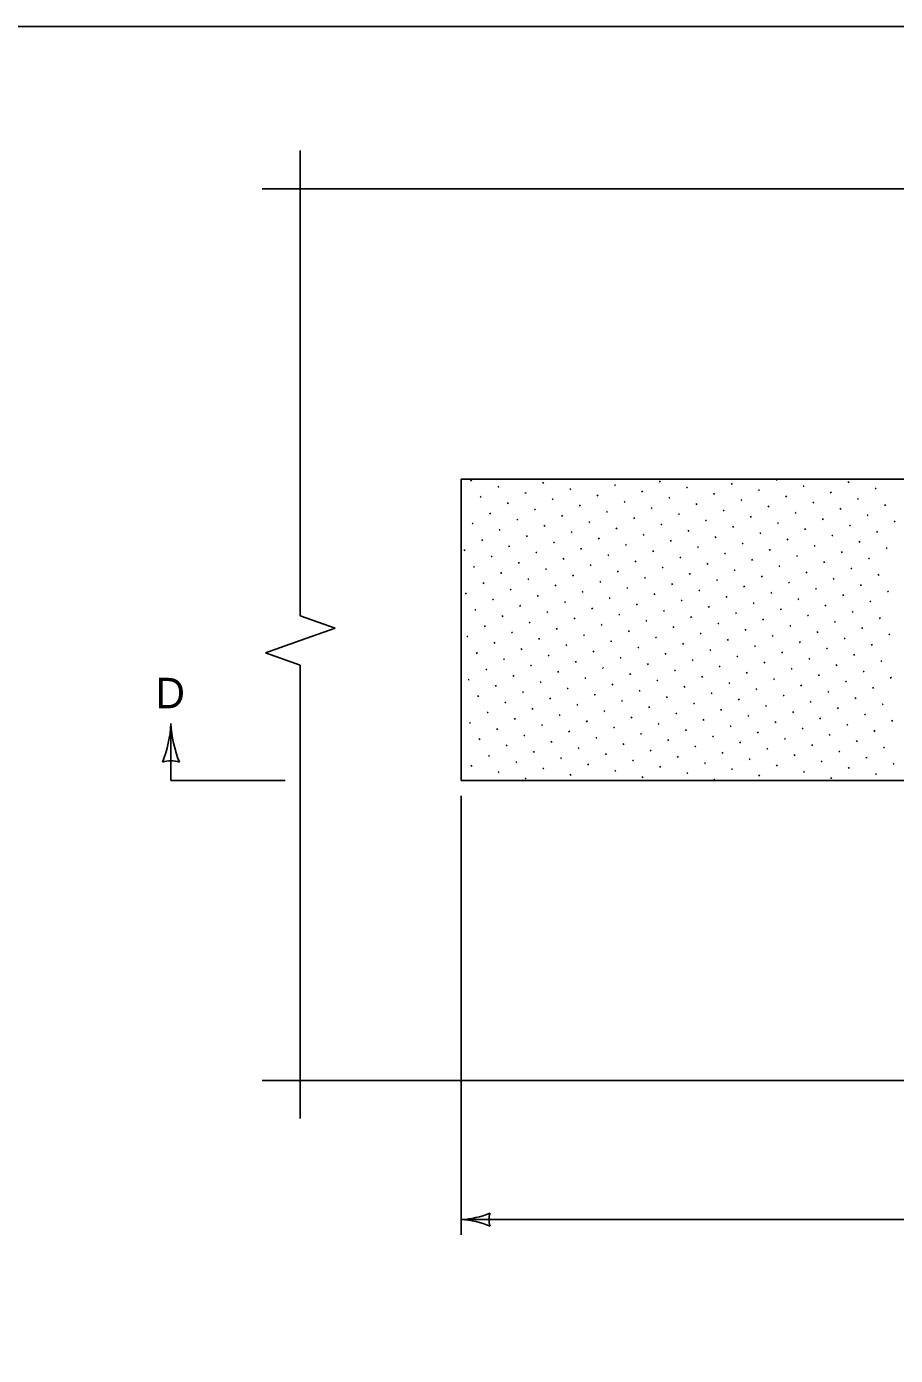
# Model space of a CAD drawing. Extents: x 49991.4 to 50021, y 49987.6 to 50011.4.
# Drawn here: x 50001.317 to 50003.6, y 49995.508 to 49998.999 of the extents above; entities that cross this region are included whole.
import ezdxf

# ---------------------------------------------------------------- set-up
doc = ezdxf.new("R2010")
doc.units = 0
for name, color, linetype in [('Level 1', 7, 'Continuous'), ('Level 2', 7, 'Continuous'), ('Level 3', 7, 'Continuous'), ('Level 6', 7, 'Continuous')]:
    doc.layers.add(name, color=color, linetype=linetype)

msp = doc.modelspace()

# ---------------------------------------------------------------- linework, layer by layer
at = {"layer": 'Level 1'}
for p, q in [((50002.4589, 49997.8102), (50013.6129, 49997.8102)), ((50002.4589, 49997.0183), (50002.4589, 49997.8102)), ((50013.6129, 49997.0183), (50002.4589, 49997.0183))]:
    msp.add_line(p, q, dxfattribs=at)
msp.add_lwpolyline([(49999.3835, 49998.9992), (50016.7501, 49998.9992), (50016.7501, 49987.7988), (49999.3835, 49987.7988)], close=True, dxfattribs=at)
at = {"layer": 'Level 3'}
for p, q in [((50002.4839, 49997.8061), (50002.487, 49997.8078)), ((50002.5553, 49997.7895), (50002.5583, 49997.7913)), ((50002.673, 49997.7997), (50002.676, 49997.8015)), ((50002.7906, 49997.8099), (50002.7911, 49997.8102)), ((50002.862, 49997.7934), (50002.865, 49997.7951)), ((50002.9797, 49997.8036), (50002.9827, 49997.8053)), ((50003.1687, 49997.7973), (50003.1717, 49997.799)), ((50003.2863, 49997.8075), (50003.2894, 49997.8092)), ((50003.3577, 49997.7909), (50003.3607, 49997.7927)), ((50003.4754, 49997.8011), (50003.4784, 49997.8029)), ((50002.5089, 49997.7628), (50002.512, 49997.7645)), ((50002.6266, 49997.773), (50002.6297, 49997.7747)), ((50002.698, 49997.7564), (50002.701, 49997.7582)), ((50002.7443, 49997.7832), (50002.7473, 49997.7849)), ((50002.8156, 49997.7666), (50002.8187, 49997.7684)), ((50002.9333, 49997.7768), (50002.9363, 49997.7786)), ((50003.0047, 49997.7603), (50003.0077, 49997.762)), ((50003.051, 49997.787), (50003.054, 49997.7888)), ((50003.1223, 49997.7705), (50003.1254, 49997.7722)), ((50003.24, 49997.7807), (50003.243, 49997.7825)), ((50003.3113, 49997.7642), (50003.3144, 49997.7659)), ((50003.429, 49997.7744), (50003.4321, 49997.7761)), ((50003.5004, 49997.7578), (50003.5034, 49997.7596)), ((50003.5467, 49997.7846), (50003.5497, 49997.7863)), ((50002.5339, 49997.7195), (50002.537, 49997.7212)), ((50002.5803, 49997.7462), (50002.5833, 49997.748)), ((50002.6516, 49997.7297), (50002.6547, 49997.7314)), ((50002.7693, 49997.7399), (50002.7723, 49997.7416)), ((50002.8406, 49997.7233), (50002.8437, 49997.7251)), ((50002.887, 49997.7501), (50002.89, 49997.7518)), ((50002.9583, 49997.7335), (50002.9613, 49997.7353)), ((50003.076, 49997.7437), (50003.079, 49997.7455)), ((50003.1473, 49997.7272), (50003.1504, 49997.7289)), ((50003.1937, 49997.754), (50003.1967, 49997.7557)), ((50003.265, 49997.7374), (50003.268, 49997.7392)), ((50003.3363, 49997.7209), (50003.3394, 49997.7226)), ((50003.3827, 49997.7476), (50003.3857, 49997.7494)), ((50003.454, 49997.7311), (50003.4571, 49997.7328)), ((50003.5717, 49997.7413), (50003.5747, 49997.743)), ((50002.4876, 49997.6927), (50002.4906, 49997.6945)), ((50002.6053, 49997.7029), (50002.6083, 49997.7047)), ((50002.6766, 49997.6864), (50002.6797, 49997.6881)), ((50002.723, 49997.7131), (50002.726, 49997.7149)), ((50002.7943, 49997.6966), (50002.7973, 49997.6983)), ((50002.912, 49997.7068), (50002.915, 49997.7085)), ((50002.9833, 49997.6902), (50002.9863, 49997.692)), ((50003.0297, 49997.717), (50003.0327, 49997.7187)), ((50003.101, 49997.7004), (50003.104, 49997.7022)), ((50003.2187, 49997.7107), (50003.2217, 49997.7124)), ((50003.29, 49997.6941), (50003.293, 49997.6959)), ((50003.4077, 49997.7043), (50003.4107, 49997.7061)), ((50003.479, 49997.6878), (50003.4821, 49997.6895)), ((50003.5254, 49997.7145), (50003.5284, 49997.7163)), ((50003.5967, 49997.698), (50003.5997, 49997.6997)), ((50002.5589, 49997.6762), (50002.562, 49997.6779)), ((50002.6303, 49997.6596), (50002.6333, 49997.6614)), ((50002.748, 49997.6698), (50002.751, 49997.6716)), ((50002.8193, 49997.6533), (50002.8223, 49997.655)), ((50002.8656, 49997.68), (50002.8687, 49997.6818)), ((50002.937, 49997.6635), (50002.94, 49997.6652)), ((50003.0547, 49997.6737), (50003.0577, 49997.6754)), ((50003.126, 49997.6571), (50003.129, 49997.6589)), ((50003.1723, 49997.6839), (50003.1754, 49997.6856)), ((50003.2437, 49997.6673), (50003.2467, 49997.6691)), ((50003.315, 49997.6508), (50003.318, 49997.6526)), ((50003.3613, 49997.6776), (50003.3644, 49997.6793)), ((50003.4327, 49997.661), (50003.4357, 49997.6628)), ((50003.5504, 49997.6712), (50003.5534, 49997.673)), ((50002.4663, 49997.6227), (50002.4693, 49997.6244)), ((50002.5126, 49997.6494), (50002.5156, 49997.6512)), ((50002.5839, 49997.6329), (50002.587, 49997.6346)), ((50002.6553, 49997.6163), (50002.6583, 49997.6181)), ((50002.7016, 49997.6431), (50002.7047, 49997.6448)), ((50002.773, 49997.6265), (50002.776, 49997.6283)), ((50002.8906, 49997.6367), (50002.8937, 49997.6385)), ((50002.962, 49997.6202), (50002.965, 49997.6219)), ((50003.0083, 49997.6469), (50003.0113, 49997.6487)), ((50003.0797, 49997.6304), (50003.0827, 49997.6321)), ((50003.1973, 49997.6406), (50003.2004, 49997.6423)), ((50003.2687, 49997.624), (50003.2717, 49997.6258)), ((50003.3863, 49997.6343), (50003.3894, 49997.636)), ((50003.4577, 49997.6177), (50003.4607, 49997.6195)), ((50003.504, 49997.6445), (50003.5071, 49997.6462)), ((50003.5754, 49997.6279), (50003.5784, 49997.6297)), ((50002.5376, 49997.6061), (50002.5406, 49997.6079)), ((50002.6089, 49997.5896), (50002.612, 49997.5913)), ((50002.7266, 49997.5998), (50002.7297, 49997.6015)), ((50002.798, 49997.5832), (50002.801, 49997.585)), ((50002.8443, 49997.61), (50002.8473, 49997.6117)), ((50002.9156, 49997.5934), (50002.9187, 49997.5952)), ((50003.0333, 49997.6036), (50003.0363, 49997.6054)), ((50003.1047, 49997.5871), (50003.1077, 49997.5888)), ((50003.151, 49997.6138), (50003.154, 49997.6156)), ((50003.2223, 49997.5973), (50003.2254, 49997.599)), ((50003.2937, 49997.5807), (50003.2967, 49997.5825)), ((50003.34, 49997.6075), (50003.343, 49997.6092)), ((50003.4113, 49997.591), (50003.4144, 49997.5927)), ((50003.529, 49997.6012), (50003.5321, 49997.6029)), ((50002.4913, 49997.5794), (50002.4943, 49997.5811)), ((50002.5626, 49997.5628), (50002.5656, 49997.5646)), ((50002.6339, 49997.5463), (50002.637, 49997.548)), ((50002.6803, 49997.573), (50002.6833, 49997.5748)), ((50002.7516, 49997.5565), (50002.7547, 49997.5582)), ((50002.8693, 49997.5667), (50002.8723, 49997.5684)), ((50002.9406, 49997.5501), (50002.9437, 49997.5519)), ((50002.987, 49997.5769), (50002.99, 49997.5786)), ((50003.0583, 49997.5603), (50003.0613, 49997.5621)), ((50003.176, 49997.5705), (50003.179, 49997.5723)), ((50003.2473, 49997.554), (50003.2504, 49997.5557)), ((50003.365, 49997.5642), (50003.368, 49997.5659)), ((50003.4363, 49997.5477), (50003.4394, 49997.5494)), ((50003.4827, 49997.5744), (50003.4857, 49997.5762)), ((50003.554, 49997.5579), (50003.5571, 49997.5596)), ((50002.5163, 49997.5361), (50002.5193, 49997.5378)), ((50002.5876, 49997.5195), (50002.5906, 49997.5213)), ((50002.7053, 49997.5297), (50002.7083, 49997.5315)), ((50002.7766, 49997.5132), (50002.7797, 49997.5149)), ((50002.823, 49997.5399), (50002.826, 49997.5417)), ((50002.8943, 49997.5234), (50002.8973, 49997.5251)), ((50003.012, 49997.5336), (50003.015, 49997.5353)), ((50003.0833, 49997.517), (50003.0863, 49997.5188)), ((50003.1297, 49997.5438), (50003.1327, 49997.5455)), ((50003.201, 49997.5272), (50003.204, 49997.529)), ((50003.2723, 49997.5107), (50003.2754, 49997.5124)), ((50003.3187, 49997.5374), (50003.3217, 49997.5392)), ((50003.39, 49997.5209), (50003.393, 49997.5226)), ((50003.5077, 49997.5311), (50003.5107, 49997.5329)), ((50003.579, 49997.5146), (50003.5821, 49997.5163)), ((50002.4699, 49997.5093), (50002.473, 49997.5111)), ((50002.5413, 49997.4928), (50002.5443, 49997.4945)), ((50002.6126, 49997.4762), (50002.6156, 49997.478)), ((50002.6589, 49997.503), (50002.662, 49997.5047)), ((50002.7303, 49997.4864), (50002.7333, 49997.4882)), ((50002.848, 49997.4966), (50002.851, 49997.4984)), ((50002.9193, 49997.4801), (50002.9223, 49997.4818)), ((50002.9656, 49997.5068), (50002.9687, 49997.5086)), ((50003.037, 49997.4903), (50003.04, 49997.492)), ((50003.1547, 49997.5005), (50003.1577, 49997.5022)), ((50003.226, 49997.4839), (50003.229, 49997.4857)), ((50003.3437, 49997.4941), (50003.3467, 49997.4959)), ((50003.415, 49997.4776), (50003.418, 49997.4793)), ((50003.4613, 49997.5043), (50003.4644, 49997.5061)), ((50003.5327, 49997.4878), (50003.5357, 49997.4896)), ((50002.4949, 49997.466), (50002.498, 49997.4678)), ((50002.5663, 49997.4495), (50002.5693, 49997.4512)), ((50002.6839, 49997.4597), (50002.687, 49997.4614)), ((50002.7553, 49997.4431), (50002.7583, 49997.4449)), ((50002.8016, 49997.4699), (50002.8047, 49997.4716)), ((50002.873, 49997.4533), (50002.876, 49997.4551)), ((50002.9906, 49997.4635), (50002.9937, 49997.4653)), ((50003.062, 49997.447), (50003.065, 49997.4487)), ((50003.1083, 49997.4737), (50003.1113, 49997.4755)), ((50003.1797, 49997.4572), (50003.1827, 49997.4589)), ((50003.251, 49997.4406), (50003.254, 49997.4424)), ((50003.2973, 49997.4674), (50003.3004, 49997.4691)), ((50003.3687, 49997.4508), (50003.3717, 49997.4526)), ((50003.4863, 49997.461), (50003.4894, 49997.4628)), ((50003.5577, 49997.4445), (50003.5607, 49997.4463)), ((50002.5199, 49997.4227), (50002.523, 49997.4245)), ((50002.5913, 49997.4062), (50002.5943, 49997.4079)), ((50002.6376, 49997.4329), (50002.6406, 49997.4347)), ((50002.7089, 49997.4164), (50002.712, 49997.4181)), ((50002.8266, 49997.4266), (50002.8297, 49997.4283)), ((50002.898, 49997.41), (50002.901, 49997.4118)), ((50002.9443, 49997.4368), (50002.9473, 49997.4385)), ((50003.0156, 49997.4202), (50003.0187, 49997.422)), ((50003.1333, 49997.4304), (50003.1363, 49997.4322)), ((50003.2047, 49997.4139), (50003.2077, 49997.4156)), ((50003.3223, 49997.4241), (50003.3254, 49997.4258)), ((50003.3937, 49997.4075), (50003.3967, 49997.4093)), ((50003.44, 49997.4343), (50003.443, 49997.436)), ((50003.5113, 49997.4177), (50003.5144, 49997.4195)), ((50002.4736, 49997.396), (50002.4766, 49997.3977)), ((50002.5449, 49997.3794), (50002.548, 49997.3812)), ((50002.6626, 49997.3896), (50002.6656, 49997.3914)), ((50002.7339, 49997.3731), (50002.737, 49997.3748)), ((50002.7803, 49997.3998), (50002.7833, 49997.4016)), ((50002.8516, 49997.3833), (50002.8547, 49997.385)), ((50002.9693, 49997.3935), (50002.9723, 49997.3952)), ((50003.0406, 49997.3769), (50003.0437, 49997.3787)), ((50003.087, 49997.4037), (50003.09, 49997.4054)), ((50003.1583, 49997.3871), (50003.1613, 49997.3889)), ((50003.2297, 49997.3706), (50003.2327, 49997.3723)), ((50003.276, 49997.3973), (50003.279, 49997.3991)), ((50003.3473, 49997.3808), (50003.3504, 49997.3825)), ((50003.465, 49997.391), (50003.468, 49997.3927)), ((50003.5363, 49997.3744), (50003.5394, 49997.3762)), ((50003.5827, 49997.4012), (50003.5857, 49997.4029)), ((50002.4986, 49997.3526), (50002.5016, 49997.3544)), ((50002.5699, 49997.3361), (50002.573, 49997.3379)), ((50002.6163, 49997.3629), (50002.6193, 49997.3646)), ((50002.6876, 49997.3463), (50002.6906, 49997.3481)), ((50002.8053, 49997.3565), (50002.8083, 49997.3583)), ((50002.8766, 49997.34), (50002.8797, 49997.3417)), ((50002.923, 49997.3667), (50002.926, 49997.3685)), ((50002.9943, 49997.3502), (50002.9973, 49997.3519)), ((50003.112, 49997.3604), (50003.115, 49997.3621)), ((50003.1833, 49997.3438), (50003.1863, 49997.3456)), ((50003.301, 49997.354), (50003.304, 49997.3558)), ((50003.3723, 49997.3375), (50003.3754, 49997.3392)), ((50003.4187, 49997.3642), (50003.4217, 49997.366)), ((50003.49, 49997.3477), (50003.493, 49997.3494)), ((50002.5236, 49997.3093), (50002.5266, 49997.3111)), ((50002.6413, 49997.3196), (50002.6443, 49997.3213)), ((50002.7126, 49997.303), (50002.7156, 49997.3048)), ((50002.7589, 49997.3298), (50002.762, 49997.3315)), ((50002.8303, 49997.3132), (50002.8333, 49997.315)), ((50002.948, 49997.3234), (50002.951, 49997.3252)), ((50003.0193, 49997.3069), (50003.0223, 49997.3086)), ((50003.0656, 49997.3336), (50003.0687, 49997.3354)), ((50003.137, 49997.3171), (50003.14, 49997.3188)), ((50003.2083, 49997.3005), (50003.2113, 49997.3023)), ((50003.2547, 49997.3273), (50003.2577, 49997.329)), ((50003.326, 49997.3107), (50003.329, 49997.3125)), ((50003.4437, 49997.3209), (50003.4467, 49997.3227)), ((50003.515, 49997.3044), (50003.518, 49997.3061)), ((50003.5613, 49997.3311), (50003.5644, 49997.3329)), ((50002.4773, 49997.2826), (50002.4803, 49997.2843)), ((50002.5486, 49997.266), (50002.5516, 49997.2678)), ((50002.5949, 49997.2928), (50002.598, 49997.2945)), ((50002.6663, 49997.2763), (50002.6693, 49997.278)), ((50002.7839, 49997.2865), (50002.787, 49997.2882)), ((50002.8553, 49997.2699), (50002.8583, 49997.2717)), ((50002.9016, 49997.2967), (50002.9047, 49997.2984)), ((50002.973, 49997.2801), (50002.976, 49997.2819)), ((50003.0906, 49997.2903), (50003.0937, 49997.2921)), ((50003.162, 49997.2738), (50003.165, 49997.2755)), ((50003.2797, 49997.284), (50003.2827, 49997.2857)), ((50003.351, 49997.2674), (50003.354, 49997.2692)), ((50003.3973, 49997.2942), (50003.4004, 49997.2959)), ((50003.4687, 49997.2776), (50003.4717, 49997.2794)), ((50003.5863, 49997.2878), (50003.5894, 49997.2896)), ((50002.5023, 49997.2393), (50002.5053, 49997.241)), ((50002.6199, 49997.2495), (50002.623, 49997.2512)), ((50002.6913, 49997.233), (50002.6943, 49997.2347)), ((50002.7376, 49997.2597), (50002.7406, 49997.2615)), ((50002.8089, 49997.2432), (50002.812, 49997.2449)), ((50002.9266, 49997.2534), (50002.9297, 49997.2551)), ((50002.998, 49997.2368), (50003.001, 49997.2386)), ((50003.0443, 49997.2636), (50003.0473, 49997.2653)), ((50003.1156, 49997.247), (50003.1187, 49997.2488)), ((50003.2333, 49997.2572), (50003.2363, 49997.259)), ((50003.3047, 49997.2407), (50003.3077, 49997.2424)), ((50003.4223, 49997.2509), (50003.4254, 49997.2526)), ((50003.4937, 49997.2343), (50003.4967, 49997.2361)), ((50003.54, 49997.2611), (50003.543, 49997.2628)), ((50002.5273, 49997.196), (50002.5303, 49997.1977)), ((50002.5736, 49997.2227), (50002.5766, 49997.2245)), ((50002.6449, 49997.2062), (50002.648, 49997.2079)), ((50002.7626, 49997.2164), (50002.7656, 49997.2182)), ((50002.8339, 49997.1999), (50002.837, 49997.2016)), ((50002.8803, 49997.2266), (50002.8833, 49997.2284)), ((50002.9516, 49997.2101), (50002.9547, 49997.2118)), ((50003.0693, 49997.2203), (50003.0723, 49997.222)), ((50003.1406, 49997.2037), (50003.1437, 49997.2055)), ((50003.187, 49997.2305), (50003.19, 49997.2322)), ((50003.2583, 49997.2139), (50003.2613, 49997.2157)), ((50003.3297, 49997.1974), (50003.3327, 49997.1991)), ((50003.376, 49997.2241), (50003.379, 49997.2259)), ((50003.4473, 49997.2076), (50003.4504, 49997.2093)), ((50003.565, 49997.2178), (50003.568, 49997.2195)), ((50002.4809, 49997.1692), (50002.4839, 49997.171)), ((50002.5986, 49997.1794), (50002.6016, 49997.1812)), ((50002.6699, 49997.1629), (50002.673, 49997.1646)), ((50002.7163, 49997.1896), (50002.7193, 49997.1914)), ((50002.7876, 49997.1731), (50002.7906, 49997.1749)), ((50002.9053, 49997.1833), (50002.9083, 49997.1851)), ((50002.9766, 49997.1668), (50002.9797, 49997.1685)), ((50003.023, 49997.1935), (50003.026, 49997.1953)), ((50003.0943, 49997.177), (50003.0973, 49997.1787)), ((50003.212, 49997.1872), (50003.215, 49997.1889)), ((50003.2833, 49997.1706), (50003.2863, 49997.1724)), ((50003.401, 49997.1808), (50003.404, 49997.1826)), ((50003.4723, 49997.1643), (50003.4754, 49997.166)), ((50003.5187, 49997.191), (50003.5217, 49997.1928)), ((50003.59, 49997.1745), (50003.593, 49997.1762)), ((50002.5059, 49997.1259), (50002.5089, 49997.1277)), ((50002.5523, 49997.1527), (50002.5553, 49997.1544)), ((50002.6236, 49997.1361), (50002.6266, 49997.1379)), ((50002.7413, 49997.1463), (50002.7443, 49997.1481)), ((50002.8126, 49997.1298), (50002.8156, 49997.1316)), ((50002.8589, 49997.1566), (50002.862, 49997.1583)), ((50002.9303, 49997.14), (50002.9333, 49997.1418)), ((50003.048, 49997.1502), (50003.051, 49997.152)), ((50003.1193, 49997.1337), (50003.1223, 49997.1354)), ((50003.1656, 49997.1604), (50003.1687, 49997.1622)), ((50003.237, 49997.1439), (50003.24, 49997.1456)), ((50003.3083, 49997.1273), (50003.3113, 49997.1291)), ((50003.3547, 49997.1541), (50003.3577, 49997.1558)), ((50003.426, 49997.1375), (50003.429, 49997.1393)), ((50003.5437, 49997.1477), (50003.5467, 49997.1495)), ((50002.5773, 49997.1094), (50002.5803, 49997.1111)), ((50002.6486, 49997.0928), (50002.6516, 49997.0946)), ((50002.6949, 49997.1196), (50002.698, 49997.1213)), ((50002.7663, 49997.103), (50002.7693, 49997.1048)), ((50002.8839, 49997.1133), (50002.887, 49997.115)), ((50002.9553, 49997.0967), (50002.9583, 49997.0985)), ((50003.0016, 49997.1235), (50003.0047, 49997.1252)), ((50003.073, 49997.1069), (50003.076, 49997.1087)), ((50003.1906, 49997.1171), (50003.1937, 49997.1189)), ((50003.262, 49997.1006), (50003.265, 49997.1023)), ((50003.3797, 49997.1108), (50003.3827, 49997.1125)), ((50003.451, 49997.0942), (50003.454, 49997.096)), ((50003.4973, 49997.121), (50003.5004, 49997.1227)), ((50003.5687, 49997.1044), (50003.5717, 49997.1062)), ((50002.5309, 49997.0826), (50002.5339, 49997.0844)), ((50002.6023, 49997.0661), (50002.6053, 49997.0678)), ((50002.7199, 49997.0763), (50002.723, 49997.078)), ((50002.7913, 49997.0597), (50002.7943, 49997.0615)), ((50002.8376, 49997.0865), (50002.8406, 49997.0882)), ((50002.9089, 49997.07), (50002.912, 49997.0717)), ((50003.0266, 49997.0802), (50003.0297, 49997.0819)), ((50003.098, 49997.0636), (50003.101, 49997.0654)), ((50003.1443, 49997.0904), (50003.1473, 49997.0921)), ((50003.2156, 49997.0738), (50003.2187, 49997.0756)), ((50003.287, 49997.0573), (50003.29, 49997.059)), ((50003.3333, 49997.084), (50003.3363, 49997.0858)), ((50003.4047, 49997.0675), (50003.4077, 49997.0692)), ((50003.5223, 49997.0777), (50003.5254, 49997.0794)), ((50003.5937, 49997.0611), (50003.5967, 49997.0629)), ((50002.4846, 49997.0559), (50002.4876, 49997.0576)), ((50002.5559, 49997.0393), (50002.5589, 49997.0411)), ((50002.6273, 49997.0228), (50002.6303, 49997.0245)), ((50002.6736, 49997.0495), (50002.6766, 49997.0513)), ((50002.7449, 49997.033), (50002.748, 49997.0347)), ((50002.8626, 49997.0432), (50002.8656, 49997.0449)), ((50002.9339, 49997.0267), (50002.937, 49997.0284)), ((50002.9803, 49997.0534), (50002.9833, 49997.0552)), ((50003.0516, 49997.0369), (50003.0547, 49997.0386)), ((50003.1693, 49997.0471), (50003.1723, 49997.0488)), ((50003.2406, 49997.0305), (50003.2437, 49997.0323)), ((50003.3583, 49997.0407), (50003.3613, 49997.0425)), ((50003.4297, 49997.0242), (50003.4327, 49997.0259)), ((50003.476, 49997.0509), (50003.479, 49997.0527)), ((50003.5473, 49997.0344), (50003.5504, 49997.0361)), ((50003.123, 49997.0203), (50003.126, 49997.0221)), ((50002.4589, 49996.9783), (50002.4589, 49995.8249)), ((50013.6132, 49995.8649), (50002.4589, 49995.8649))]:
    msp.add_line(p, q, dxfattribs=at)
for centre, radius, start, end in [((50001.4003, 49997.1805), 0.2964, 337.456, 357.6395), ((50002.0067, 49997.1836), 0.3107, 182.8273, 202.0772), ((50001.6964, 49996.9973), 0.073, 72.1388, 107.8612), ((50002.4474, 49996.0977), 0.233, 272.8273, 292.0772), ((50002.5871, 49995.8649), 0.0548, 162.1388, 197.8612), ((50002.4497, 49995.6428), 0.2223, 67.456, 87.6395)]:
    msp.add_arc(centre, radius, start, end, dxfattribs=at)
at = {"layer": 'Level 6'}
for p, q in [((50002.0365, 49998.6733), (50002.0364, 49997.4509)), ((50004.8695, 49998.5733), (50001.9365, 49998.5733)), ((50002.1278, 49997.4185), (50002.0364, 49997.4509)), ((50002.1278, 49997.4185), (50002.0364, 49997.3861)), ((50002.0364, 49997.3861), (50001.945, 49997.3537)), ((50002.0364, 49997.3213), (50001.945, 49997.3537)), ((50002.0364, 49997.3213), (50002.0364, 49996.1307)), ((50001.6964, 49997.0183), (50001.6964, 49997.1683)), ((50001.9964, 49997.0183), (50001.6964, 49997.0183)), ((50004.8695, 49996.2307), (50001.9365, 49996.2307))]:
    msp.add_line(p, q, dxfattribs=at)

# ---------------------------------------------------------------- texts
at = {"layer": 'Level 2'}
msp.add_text('D', height=0.08, dxfattribs=at).set_placement((50001.656, 49997.2083))

doc.saveas('drawing.dxf')
